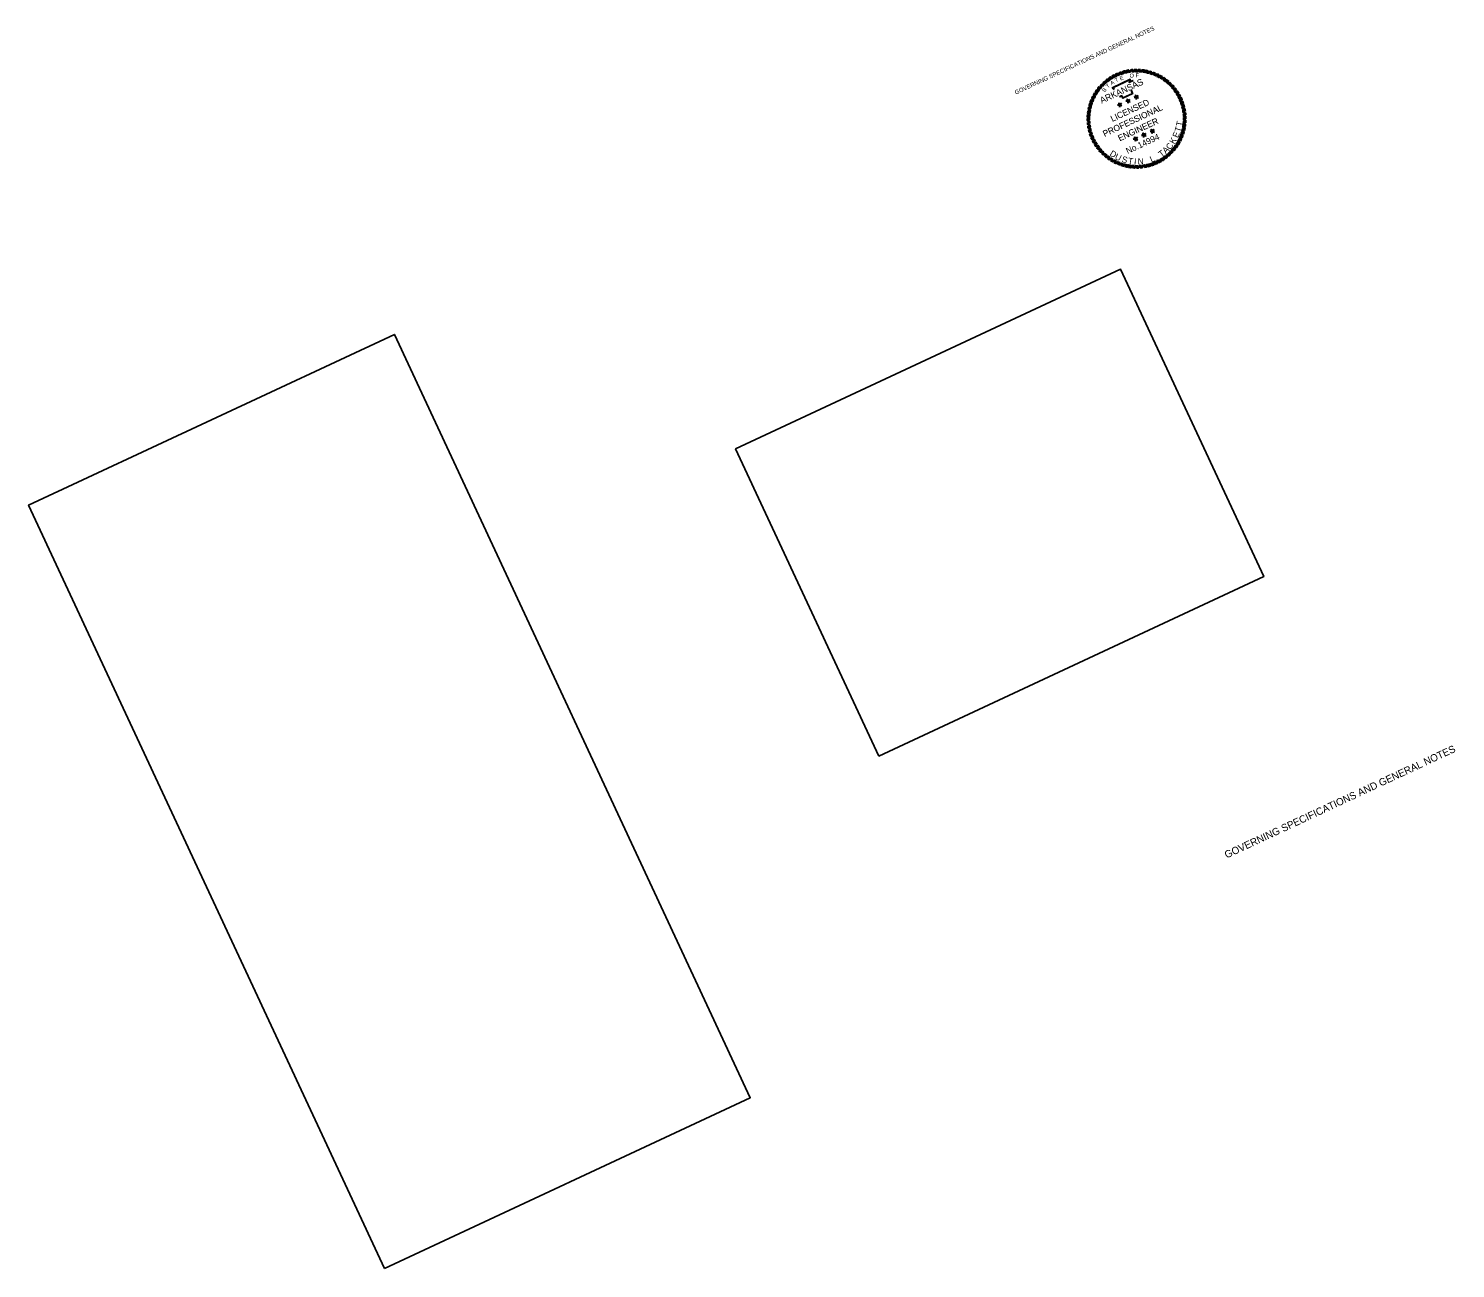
# Model space of a CAD drawing. Extents: x -22487163 to -22480035, y -237910427 to -237906052.
# Drawn here: x -22483544 to -22480035, y -237909101 to -237906052 of the extents above; entities that cross this region are included whole.
import ezdxf

# ---------------------------------------------------------------- set-up
doc = ezdxf.new("R2010")
doc.units = 0
for name, color, linetype in [('53', 7, 'Continuous'), ('54', 7, 'Continuous'), ('Default', 7, 'Continuous')]:
    doc.layers.add(name, color=color, linetype=linetype)

# ---------------------------------------------------------------- blocks, each defined once
blk = doc.blocks.new('STAR')
at = {"layer": 'Default'}
for p, q in [((0.059, 0.019), (-0.059, 0.019)), ((-0.059, 0.019), (0.036, -0.05)), ((0, 0.062), (-0.037, -0.05)), ((-0.036, -0.05), (0.059, 0.019)), ((-0.008, 0), (0.009, 0)), ((0.036, -0.05), (0, 0.062)), ((0, 0.006), (0, -0.008))]:
    blk.add_line(p, q, dxfattribs=at)
blk = doc.blocks.new('RP')
at = {"layer": 'Default'}
for p, q in [((-0.078, 1.266), (0.003, 1.33)), ((-0.058, 1.267), (0.022, 1.33)), ((-0.038, 1.267), (0.04, 1.329)), ((-0.018, 1.268), (0.059, 1.329))]:
    blk.add_line(p, q, dxfattribs=at)
for radius, start, end in [(1.268, 90.7933, 93.5307), (1.33, 87.4562, 89.8699)]:
    blk.add_arc((0, 0), radius, start, end, dxfattribs=at)

msp = doc.modelspace()

# ---------------------------------------------------------------- linework, layer by layer
at = {"layer": '54'}
for points in [[(-22481453.4, -237907841.2), (-22480506.4, -237907399.6), (-22480858.6, -237906644.3), (-22481805.6, -237907085.9)], [(-22482669.2, -237909100.7), (-22481769.5, -237908681.1), (-22482644.6, -237906804.3), (-22483544.3, -237907223.9)]]:
    msp.add_lwpolyline(points, close=True, dxfattribs=at)
at = {"layer": 'Default'}
for points in [[(-22480874.2, -237906202.3), (-22480879.3, -237906197.9), (-22480834.9, -237906177.1), (-22480836.4, -237906183.5), (-22480833.4, -237906182.1), (-22480830.9, -237906180.9), (-22480828.3, -237906180)], [(-22480874.1, -237906202.2), (-22480879.2, -237906197.8), (-22480834.7, -237906177.2), (-22480836.3, -237906183.6), (-22480833.3, -237906182.2), (-22480830.8, -237906181), (-22480828.1, -237906180.1)], [(-22480873.7, -237906201.7), (-22480877.9, -237906198.1), (-22480836, -237906178.5), (-22480837.6, -237906185), (-22480833.1, -237906182.8), (-22480830.6, -237906181.6), (-22480828, -237906180.7)], [(-22480873.6, -237906201.6), (-22480877.8, -237906198), (-22480835.9, -237906178.6), (-22480837.4, -237906185), (-22480832.9, -237906182.9), (-22480830.5, -237906181.7), (-22480827.9, -237906180.8)], [(-22480830.6, -237906204.6), (-22480831.1, -237906205.6), (-22480830.9, -237906206.6), (-22480830.1, -237906209.1), (-22480828.6, -237906212.1), (-22480853.4, -237906223.7), (-22480855.4, -237906219.6), (-22480855.8, -237906218.6), (-22480857, -237906218.8), (-22480860.5, -237906220.4), (-22480861.6, -237906219.8)], [(-22480830.5, -237906204.7), (-22480831, -237906205.7), (-22480830.8, -237906206.7), (-22480830, -237906209.1), (-22480828.6, -237906212.2), (-22480853.4, -237906223.7), (-22480855.4, -237906219.5), (-22480855.8, -237906218.6), (-22480856.9, -237906218.8), (-22480860.5, -237906220.4), (-22480861.5, -237906219.7)], [(-22480831.3, -237906204.3), (-22480831.9, -237906205.5), (-22480831.6, -237906206.8), (-22480830.8, -237906209.3), (-22480829.7, -237906211.8), (-22480853.1, -237906222.7), (-22480854.7, -237906219.2), (-22480855.3, -237906217.8), (-22480857.2, -237906218), (-22480860.4, -237906219.6), (-22480861.1, -237906219.1)], [(-22480831.2, -237906204.4), (-22480831.8, -237906205.6), (-22480831.6, -237906206.9), (-22480830.7, -237906209.4), (-22480829.6, -237906211.8), (-22480853.1, -237906222.7), (-22480854.7, -237906219.2), (-22480855.3, -237906217.8), (-22480857.2, -237906218), (-22480860.4, -237906219.5), (-22480861.1, -237906219.1)]]:
    msp.add_lwpolyline(points, dxfattribs=at)

# ---------------------------------------------------------------- block references
for name, p, xscale, yscale, rotation in [('RP', (-22480819.2, -237906274), 91.1765534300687, 91.17655343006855, 20.50000010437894), ('RP', (-22480819.4, -237906274.1), 91.17655343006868, 91.17655343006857, 20.304199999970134), ('RP', (-22480819.2, -237906274), 91.1765534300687, 91.17655343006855, 16.00000010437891), ('RP', (-22480819.4, -237906274.1), 91.1765534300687, 91.17655343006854, 15.804199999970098), ('RP', (-22480819.2, -237906274), 91.17655343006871, 91.17655343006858, 11.500000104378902), ('RP', (-22480819.4, -237906274.1), 91.17655343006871, 91.1765534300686, 11.304199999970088), ('RP', (-22480819.2, -237906274), 91.17655343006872, 91.17655343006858, 7.000000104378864), ('RP', (-22480819.4, -237906274.1), 91.1765534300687, 91.17655343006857, 6.804199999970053), ('RP', (-22480819.2, -237906274), 91.17655343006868, 91.17655343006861, 2.500000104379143), ('RP', (-22480819.4, -237906274.1), 91.17655343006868, 91.17655343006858, 2.30419999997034), ('RP', (-22480819.2, -237906274), 91.17655343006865, 91.17655343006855, -1.999999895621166), ('RP', (-22480819.4, -237906274.1), 91.17655343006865, 91.17655343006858, -2.19580000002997), ('RP', (-22480819.2, -237906274), 91.1765534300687, 91.17655343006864, -6.499999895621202), ('RP', (-22480819.4, -237906274.1), 91.17655343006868, 91.17655343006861, -6.695800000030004), ('RP', (-22480819.2, -237906274), 91.17655343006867, 91.17655343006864, -10.99999989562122), ('RP', (-22480819.4, -237906274.1), 91.17655343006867, 91.17655343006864, -11.195800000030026), ('RP', (-22480819.2, -237906274), 91.17655343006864, 91.1765534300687, -15.499999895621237), ('RP', (-22480819.4, -237906274.1), 91.17655343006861, 91.17655343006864, -15.695800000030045), ('RP', (-22480819.2, -237906274), 91.17655343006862, 91.17655343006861, -19.99999989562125), ('RP', (-22480819.4, -237906274.1), 91.17655343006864, 91.1765534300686, -20.195800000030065), ('RP', (-22480819.2, -237906274), 91.1765534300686, 91.17655343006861, -24.499999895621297), ('RP', (-22480819.4, -237906274.1), 91.1765534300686, 91.17655343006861, -24.695800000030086), ('RP', (-22480819.4, -237906274.1), 91.17655343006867, 91.17655343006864, 51.8041999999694), ('RP', (-22480819.2, -237906274), 91.17655343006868, 91.17655343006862, 52.000000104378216), ('RP', (-22480819.2, -237906274), 91.17655343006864, 91.1765534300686, 47.500000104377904), ('RP', (-22480819.4, -237906274.1), 91.17655343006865, 91.17655343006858, 47.30419999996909), ('RP', (-22480819.2, -237906274), 91.17655343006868, 91.17655343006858, 43.00000010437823), ('RP', (-22480819.4, -237906274.1), 91.17655343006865, 91.17655343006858, 42.80419999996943), ('RP', (-22480819.2, -237906274), 91.17655343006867, 91.17655343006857, 38.50000010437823), ('RP', (-22480819.4, -237906274.1), 91.17655343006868, 91.17655343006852, 38.304199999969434), ('RP', (-22480819.2, -237906274), 91.17655343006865, 91.17655343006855, 34.000000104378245), ('RP', (-22480819.4, -237906274.1), 91.17655343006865, 91.17655343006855, 33.804199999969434), ('RP', (-22480819.2, -237906274), 91.17655343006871, 91.17655343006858, 29.500000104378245), ('RP', (-22480819.4, -237906274.1), 91.17655343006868, 91.17655343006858, 29.30419999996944), ('RP', (-22480819.2, -237906274), 91.17655343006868, 91.17655343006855, 25.00000010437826), ('RP', (-22480819.4, -237906274.1), 91.17655343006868, 91.17655343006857, 24.804199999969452), ('RP', (-22480819.2, -237906274), 91.17655343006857, 91.17655343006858, -28.999999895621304), ('RP', (-22480819.4, -237906274.1), 91.17655343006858, 91.17655343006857, -29.19580000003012), ('RP', (-22480819.2, -237906274), 91.17655343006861, 91.17655343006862, -33.49999989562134), ('RP', (-22480819.4, -237906274.1), 91.17655343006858, 91.17655343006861, -33.69580000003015), ('RP', (-22480819.2, -237906274), 91.17655343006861, 91.17655343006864, -37.99999989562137), ('RP', (-22480819.4, -237906274.1), 91.17655343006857, 91.17655343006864, -38.19580000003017), ('RP', (-22480819.2, -237906274), 91.1765534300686, 91.17655343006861, -42.49999989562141), ('RP', (-22480819.4, -237906274.1), 91.1765534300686, 91.17655343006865, -42.69580000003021), ('RP', (-22480819.2, -237906274), 91.17655343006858, 91.17655343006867, -46.99999989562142), ('RP', (-22480819.4, -237906274.1), 91.17655343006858, 91.17655343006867, -47.19580000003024), ('RP', (-22480819.2, -237906274), 91.17655343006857, 91.1765534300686, -51.49999989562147), ('RP', (-22480819.4, -237906274.1), 91.1765534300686, 91.17655343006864, -51.69580000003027), ('RP', (-22480819.4, -237906274.1), 91.17655343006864, 91.17655343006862, 69.80419999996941), ('RP', (-22480819.2, -237906274), 91.17655343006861, 91.17655343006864, 70.0000001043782), ('RP', (-22480819.4, -237906274.1), 91.17655343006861, 91.1765534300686, 65.30419999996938), ('RP', (-22480819.2, -237906274), 91.17655343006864, 91.17655343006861, 65.50000010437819), ('RP', (-22480819.4, -237906274.1), 91.17655343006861, 91.17655343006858, 60.80419999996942), ('RP', (-22480819.2, -237906274), 91.17655343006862, 91.17655343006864, 61.000000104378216), ('RP', (-22480819.2, -237906274), 91.17655343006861, 91.17655343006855, 56.500000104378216), ('RP', (-22480819.4, -237906274.1), 91.17655343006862, 91.17655343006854, 56.304199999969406), ('STAR', (-22480840, -237906230.3), 91.17655343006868, 91.17655343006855, 25.00000010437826), ('STAR', (-22480840, -237906230.3), 91.17655343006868, 91.17655343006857, 24.804199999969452), ('STAR', (-22480819.5, -237906220.7), 91.17655343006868, 91.17655343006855, 25.00000010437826), ('STAR', (-22480819.5, -237906220.9), 91.17655343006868, 91.17655343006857, 24.804199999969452), ('RP', (-22480819.2, -237906274), 91.17655343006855, 91.17655343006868, -55.999999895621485), ('RP', (-22480819.4, -237906274.1), 91.17655343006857, 91.17655343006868, -56.195800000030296), ('RP', (-22480819.2, -237906274), 91.17655343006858, 91.17655343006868, -60.49999989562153), ('RP', (-22480819.4, -237906274.1), 91.17655343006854, 91.17655343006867, -60.69580000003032), ('RP', (-22480819.2, -237906274), 91.17655343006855, 91.1765534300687, -64.99999989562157), ('RP', (-22480819.4, -237906274.1), 91.17655343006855, 91.1765534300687, -65.19580000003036), ('RP', (-22480819.2, -237906274), 91.1765534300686, 91.17655343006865, -69.49999989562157), ('RP', (-22480819.4, -237906274.1), 91.17655343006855, 91.17655343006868, -69.69580000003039), ('RP', (-22480819.4, -237906274.1), 91.17655343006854, 91.17655343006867, 87.80419999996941), ('RP', (-22480819.4, -237906274.1), 91.17655343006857, 91.17655343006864, 83.30419999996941), ('RP', (-22480819.2, -237906274), 91.1765534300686, 91.17655343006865, 88.00000010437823), ('RP', (-22480819.2, -237906274), 91.17655343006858, 91.17655343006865, 83.50000010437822), ('RP', (-22480819.4, -237906274.1), 91.17655343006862, 91.17655343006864, 78.80419999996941), ('RP', (-22480819.2, -237906274), 91.17655343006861, 91.17655343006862, 79.00000010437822), ('RP', (-22480819.4, -237906274.1), 91.17655343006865, 91.17655343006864, 74.30419999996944), ('RP', (-22480819.2, -237906274), 91.17655343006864, 91.17655343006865, 74.50000010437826), ('STAR', (-22480860.5, -237906239.8), 91.17655343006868, 91.17655343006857, 24.804199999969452), ('STAR', (-22480860.4, -237906239.8), 91.17655343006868, 91.17655343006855, 25.00000010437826), ('RP', (-22480819.4, -237906274.1), 91.17655343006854, 91.17655343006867, -74.19580000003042), ('RP', (-22480819.2, -237906274), 91.17655343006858, 91.17655343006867, -73.9999998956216), ('RP', (-22480819.2, -237906274), 91.17655343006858, 91.17655343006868, -78.49999989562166), ('RP', (-22480819.4, -237906274.1), 91.17655343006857, 91.17655343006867, -78.69580000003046), ('RP', (-22480819.4, -237906274.1), 91.17655343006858, 91.17655343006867, -83.19580000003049), ('RP', (-22480819.2, -237906274), 91.17655343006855, 91.17655343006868, -82.99999989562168), ('RP', (-22480819.4, -237906274.1), 91.17655343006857, 91.1765534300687, -87.69580000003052), ('RP', (-22480819.2, -237906274), 91.17655343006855, 91.17655343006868, -87.49999989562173), ('RP', (-22480819.4, -237906274.1), 91.17655343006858, 91.17655343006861, 92.3041999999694), ('RP', (-22480819.2, -237906274), 91.1765534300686, 91.17655343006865, 92.50000010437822), ('RP', (-22480819.4, -237906274.1), 91.17655343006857, 91.17655343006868, 96.80419999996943), ('RP', (-22480819.2, -237906274), 91.17655343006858, 91.17655343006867, 97.00000010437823), ('RP', (-22480819.4, -237906274.1), 91.17655343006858, 91.17655343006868, 101.30419999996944), ('RP', (-22480819.2, -237906274), 91.17655343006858, 91.17655343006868, 101.50000010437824), ('RP', (-22480819.4, -237906274.1), 91.17655343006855, 91.17655343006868, 105.80419999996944), ('RP', (-22480819.2, -237906274), 91.17655343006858, 91.17655343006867, 106.00000010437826), ('STAR', (-22480780.7, -237906304.8), 91.17655343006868, 91.17655343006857, 24.804199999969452), ('STAR', (-22480780.4, -237906304.6), 91.17655343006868, 91.17655343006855, 25.00000010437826), ('RP', (-22480819.4, -237906274.1), 91.17655343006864, 91.17655343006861, -105.69580000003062), ('RP', (-22480819.2, -237906274), 91.17655343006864, 91.17655343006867, -105.49999989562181), ('RP', (-22480819.4, -237906274.1), 91.17655343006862, 91.17655343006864, -101.19580000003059), ('RP', (-22480819.2, -237906274), 91.17655343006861, 91.17655343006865, -100.99999989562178), ('RP', (-22480819.4, -237906274.1), 91.17655343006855, 91.17655343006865, -96.69580000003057), ('RP', (-22480819.2, -237906274), 91.17655343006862, 91.17655343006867, -96.49999989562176), ('RP', (-22480819.4, -237906274.1), 91.17655343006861, 91.1765534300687, -92.19580000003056), ('RP', (-22480819.2, -237906274), 91.17655343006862, 91.17655343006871, -91.99999989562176), ('RP', (-22480819.4, -237906274.1), 91.17655343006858, 91.17655343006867, 110.30419999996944), ('RP', (-22480819.2, -237906274), 91.17655343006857, 91.1765534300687, 110.50000010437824), ('RP', (-22480819.4, -237906274.1), 91.17655343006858, 91.17655343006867, 114.80419999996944), ('RP', (-22480819.2, -237906274), 91.1765534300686, 91.17655343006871, 115.00000010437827), ('RP', (-22480819.4, -237906274.1), 91.17655343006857, 91.1765534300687, 119.30419999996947), ('RP', (-22480819.2, -237906274), 91.1765534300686, 91.17655343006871, 119.50000010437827), ('RP', (-22480819.4, -237906274.1), 91.17655343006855, 91.17655343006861, 123.80419999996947), ('RP', (-22480819.2, -237906274), 91.17655343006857, 91.17655343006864, 124.0000001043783), ('STAR', (-22480821.7, -237906323.7), 91.17655343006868, 91.17655343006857, 24.804199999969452), ('STAR', (-22480821.3, -237906323.6), 91.17655343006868, 91.17655343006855, 25.00000010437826), ('STAR', (-22480801.2, -237906314.3), 91.17655343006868, 91.17655343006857, 24.804199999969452), ('STAR', (-22480800.9, -237906314.1), 91.17655343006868, 91.17655343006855, 25.00000010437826), ('RP', (-22480819.4, -237906274.1), 91.17655343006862, 91.17655343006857, -123.6958000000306), ('RP', (-22480819.2, -237906274), 91.17655343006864, 91.17655343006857, -123.49999989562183), ('RP', (-22480819.4, -237906274.1), 91.17655343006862, 91.17655343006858, -119.1958000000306), ('RP', (-22480819.2, -237906274), 91.17655343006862, 91.17655343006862, -118.99999989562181), ('RP', (-22480819.4, -237906274.1), 91.17655343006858, 91.17655343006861, -114.69580000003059), ('RP', (-22480819.2, -237906274), 91.17655343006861, 91.17655343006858, -114.49999989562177), ('RP', (-22480819.4, -237906274.1), 91.17655343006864, 91.17655343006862, -110.1958000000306), ('RP', (-22480819.2, -237906274), 91.17655343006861, 91.17655343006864, -109.99999989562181), ('RP', (-22480819.4, -237906274.1), 91.17655343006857, 91.17655343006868, 128.30419999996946), ('RP', (-22480819.2, -237906274), 91.17655343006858, 91.17655343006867, 128.50000010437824), ('RP', (-22480819.4, -237906274.1), 91.17655343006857, 91.17655343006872, 132.80419999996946), ('RP', (-22480819.2, -237906274), 91.17655343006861, 91.1765534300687, 133.00000010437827), ('RP', (-22480819.4, -237906274.1), 91.17655343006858, 91.17655343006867, 137.30419999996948), ('RP', (-22480819.2, -237906274), 91.17655343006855, 91.17655343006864, 137.5000001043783), ('RP', (-22480819.4, -237906274.1), 91.17655343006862, 91.17655343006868, 141.80419999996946), ('RP', (-22480819.2, -237906274), 91.17655343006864, 91.17655343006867, 142.00000010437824), ('RP', (-22480819.4, -237906274.1), 91.17655343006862, 91.17655343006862, 146.30419999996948), ('RP', (-22480819.2, -237906274), 91.17655343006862, 91.17655343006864, 146.5000001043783), ('RP', (-22480819.4, -237906274.1), 91.17655343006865, 91.17655343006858, -150.6958000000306), ('RP', (-22480819.2, -237906274), 91.1765534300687, 91.17655343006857, -150.4999998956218), ('RP', (-22480819.4, -237906274.1), 91.17655343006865, 91.17655343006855, -146.19580000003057), ('RP', (-22480819.2, -237906274), 91.17655343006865, 91.17655343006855, -145.99999989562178), ('RP', (-22480819.4, -237906274.1), 91.17655343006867, 91.17655343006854, -141.69580000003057), ('RP', (-22480819.2, -237906274), 91.17655343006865, 91.17655343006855, -141.49999989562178), ('RP', (-22480819.4, -237906274.1), 91.17655343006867, 91.17655343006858, -137.19580000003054), ('RP', (-22480819.2, -237906274), 91.1765534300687, 91.17655343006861, -136.99999989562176), ('RP', (-22480819.4, -237906274.1), 91.17655343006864, 91.17655343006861, -132.69580000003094), ('RP', (-22480819.2, -237906274), 91.17655343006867, 91.1765534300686, -132.49999989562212), ('RP', (-22480819.4, -237906274.1), 91.17655343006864, 91.17655343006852, -128.19580000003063), ('RP', (-22480819.2, -237906274), 91.17655343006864, 91.17655343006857, -127.99999989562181), ('RP', (-22480819.4, -237906274.1), 91.17655343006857, 91.1765534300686, 150.80419999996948), ('RP', (-22480819.2, -237906274), 91.1765534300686, 91.17655343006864, 151.0000001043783), ('RP', (-22480819.4, -237906274.1), 91.1765534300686, 91.17655343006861, 155.30419999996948), ('RP', (-22480819.2, -237906274), 91.17655343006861, 91.17655343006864, 155.50000010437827), ('RP', (-22480819.4, -237906274.1), 91.17655343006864, 91.17655343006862, 159.80419999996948), ('RP', (-22480819.2, -237906274), 91.17655343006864, 91.17655343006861, 160.0000001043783), ('RP', (-22480819.4, -237906274.1), 91.17655343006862, 91.17655343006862, 164.30419999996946), ('RP', (-22480819.2, -237906274), 91.17655343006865, 91.17655343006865, 164.50000010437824), ('RP', (-22480819.4, -237906274.1), 91.17655343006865, 91.17655343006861, 168.80419999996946), ('RP', (-22480819.2, -237906274), 91.17655343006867, 91.1765534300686, 169.00000010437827), ('RP', (-22480819.4, -237906274.1), 91.17655343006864, 91.17655343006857, 173.30419999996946), ('RP', (-22480819.2, -237906274), 91.17655343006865, 91.17655343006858, 173.5000001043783), ('RP', (-22480819.4, -237906274.1), 91.17655343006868, 91.17655343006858, 177.80419999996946), ('RP', (-22480819.2, -237906274), 91.17655343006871, 91.17655343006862, 178.00000010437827), ('RP', (-22480819.4, -237906274.1), 91.17655343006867, 91.17655343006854, -177.6958000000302), ('RP', (-22480819.2, -237906274), 91.17655343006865, 91.17655343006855, -177.49999989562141), ('RP', (-22480819.4, -237906274.1), 91.17655343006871, 91.17655343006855, -173.19580000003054), ('RP', (-22480819.2, -237906274), 91.1765534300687, 91.1765534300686, -172.99999989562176), ('RP', (-22480819.4, -237906274.1), 91.17655343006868, 91.17655343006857, -168.69580000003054), ('RP', (-22480819.2, -237906274), 91.17655343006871, 91.17655343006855, -168.49999989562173), ('RP', (-22480819.4, -237906274.1), 91.17655343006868, 91.17655343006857, -164.19580000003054), ('RP', (-22480819.2, -237906274), 91.17655343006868, 91.17655343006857, -163.99999989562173), ('RP', (-22480819.4, -237906274.1), 91.17655343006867, 91.17655343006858, -159.69580000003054), ('RP', (-22480819.2, -237906274), 91.1765534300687, 91.17655343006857, -159.49999989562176), ('RP', (-22480819.4, -237906274.1), 91.17655343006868, 91.17655343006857, -155.19580000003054), ('RP', (-22480819.2, -237906274), 91.17655343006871, 91.1765534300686, -154.99999989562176)]:
    msp.add_blockref(name, p, dxfattribs=dict(at, xscale=xscale, yscale=yscale, rotation=rotation))

# ---------------------------------------------------------------- texts
at = {"layer": '53'}
msp.add_text('GOVERNING SPECIFICATIONS AND GENERAL NOTES', height=18, rotation=25, dxfattribs=at).set_placement((-22480597.9, -237908093))
at = {"layer": '54'}
msp.add_text('GOVERNING SPECIFICATIONS AND GENERAL NOTES', height=10.552, rotation=25, dxfattribs=at).set_placement((-22481116.2, -237906215.2))
at = {"layer": 'Default'}
for s, height, rotation, p in [('ARKANSAS', 15.79, 25, (-22480905.1, -237906237.4)), ('ARKANSAS', 15.79, 24.8042, (-22480905.2, -237906237.3)), ('T', 9.67, 41.9015, (-22480889.8, -237906199.9)), ('T', 9.67, 41.7057, (-22480889.8, -237906199.8)), ('A', 9.67, 33.6788, (-22480880.5, -237906192.2)), ('A', 9.67, 33.483, (-22480880.4, -237906192.1)), ('T', 9.67, 26.4789, (-22480870, -237906185.2)), ('T', 9.67, 26.2831, (-22480869.9, -237906185.1)), ('E', 9.67, 21.672, (-22480858.6, -237906180.2)), ('E', 9.67, 21.4762, (-22480858.5, -237906180.2)), ('O', 9.67, 6.2218, (-22480836, -237906173.3)), ('O', 9.67, 6.026, (-22480835.8, -237906173.3)), ('F', 9.67, 0.3628, (-22480822, -237906172.4)), ('F', 9.67, 0.167, (-22480821.8, -237906172.5)), ('S', 9.67, 44.7726, (-22480898.7, -237906210.1)), ('S', 9.67, 44.5768, (-22480898.6, -237906210)), ('LICENSED', 15.28, 24.8042, (-22480879.1, -237906282)), ('LICENSED', 15.28, 25, (-22480878.9, -237906282.1)), ('PROFESSIONAL', 15.285, 24.8042, (-22480898.1, -237906318.9)), ('PROFESSIONAL', 15.285, 25, (-22480897.8, -237906319.1)), ('ENGINEER', 15.28, 24.8042, (-22480860.9, -237906329.9)), ('ENGINEER', 15.28, 25, (-22480860.6, -237906329.9)), ('T', 15.3, 73.0746, (-22480711.5, -237906308.2)), ('T', 15.3, 79.3036, (-22480707.3, -237906293.8)), ('No.14994', 15.22, 25, (-22480841.1, -237906361.1)), ('C', 15.3, 58.6577, (-22480735.5, -237906351.6)), ('K', 15.3, 60.1218, (-22480726.4, -237906337.8)), ('E', 15.3, 67.4392, (-22480717.6, -237906322.4)), ('D', 15.3, 327.9045, (-22480887, -237906363.6)), ('U', 15.3, 334.8131, (-22480874.3, -237906372.7)), ('S', 15.3, 345.368, (-22480857.1, -237906380.4)), ('T', 15.3, 350.101, (-22480841.5, -237906384.7)), ('N', 15.3, 2.2539, (-22480816.2, -237906386.9)), ('L', 15.3, 23.474, (-22480782.7, -237906382.1)), ('T', 15.3, 36.7303, (-22480758.4, -237906369.5)), ('A', 15.3, 44.3817, (-22480747.3, -237906361)), ('I', 15.3, 355.8687, (-22480826, -237906386.9)), ('.', 15.3, 29.1489, (-22480771.1, -237906377.5))]:
    msp.add_text(s, height=height, rotation=rotation, dxfattribs=at).set_placement(p)

doc.saveas('drawing.dxf')
